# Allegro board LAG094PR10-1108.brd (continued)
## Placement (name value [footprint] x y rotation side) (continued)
PLH11  -  [5A_Z80_0805_2P]  156.75 63.52 270 bottom
PLM01  1UH_11A_20%_7X7X3_M  [L_7X7X3_M_2P]  19.27 98.76 90 bottom
PLM11  -  [5A_Z80_0805_2P]  26.67 110.05 180 bottom
PLZ1  0.47UH_NA__12.2A_20%  [L_5X5X3_M]  85.51 117.32 270 bottom
PLZ11  -  [5A_Z80_0805_2P]  87.28 125.69 270 bottom
PQ1  -  [FDV301N-G_SOT23-3]  74.94 147.12 270 top
PQ2  -  [MMST3904-7-F_SOT323-3]  79.54 143.25 0 top
PQ11  -  [2N7002KW_SOT323-3]  190.62 42.9 270 top
PQ12  -  [L2N7002DW1T1G_SC88-6]  182.99 66.22 180 top
PQ13  -  [2N7002KDW_SOT363-6]  184.55 64.41 0 top
PQB03  -  [2N7002KW_SOT323-3]  177.06 69.38 90 top
PQB11  -  [EMB04N03H_EDFN5X6-8-5]  165.91 63.3 90 top
PQB12  -  [EMB04N03H_EDFN5X6-8-5]  174.58 66.87 270 top
PQB13  -  [EMB04N03H_EDFN5X6-8-5]  175.81 54.12 90 bottom
PQB25  AON7506_DFN33-8-5  [AON7702L_DFN8-5]  185.44 48.57 270 bottom
PQB26  AON7408L_DFN8-5  [AON7702L_DFN8-5]  182.57 50.28 90 bottom
PQB28  -  [LMUN5113T1G_SOT323-3]  169.95 44.89 0 top
PQB29  -  [LTC015EUBFS8TL_UMT3F]  169.85 48.89 180 top
PQB31  2N7002KW_SOT323-3  [DMN65D8LW-7_SOT323-3]  190.41 49.57 0 top
PQB32  -  [RUM002N02GT2L_VMT3]  200.26 55.62 0 top
PQB33  -  [RUM002N02GT2L_VMT3]  196.76 54.94 0 top
PQG1  -  [AON6380_DFN5X6-8-5]  101.63 117.92 180 bottom
PQG2  AON6314_N_DFN56-8-5  [Q_N_DFN56-8-5]  91.73 123.44 0 bottom
PQM01  -  [AONH36334_DFN3X3A8-10]  23.89 106.18 0 bottom
PQZ1  -  [AONH36334_DFN3X3A8-10]  87.35 121.94 270 bottom
PR1  33_0402_5%  [R_0402]  78.95 148.59 0 top
PR3  100K_0402_1%  [R_0402]  78.95 147.76 0 top
PR4  10K_0402_1%  [R_0402]  81.25 145.11 270 top
PR5  2.2K_0402_5%  [R_0402]  82.44 148.59 0 top
PR6  15K_0402_1%  [R_0402]  79.87 146.3 180 top
PR7  100K_0402_1%  [R_0402]  80.79 142.93 0 top
PR9  16.2K_0402_1%  [R_0402]  114.22 38.29 180 bottom
PR31  0_0402_5%  [R_0402]  186.09 62.4 90 top
PR32  3.3K_1206_5%  [R_1206]  187.55 67.11 270 top
PR33  10K_0402_1%  [R_0402]  182.58 62.42 0 top
PR34  1M_0402_1%  [R_0402]  186.04 68 180 top
PR35  0_0402_5%  [R_0402]  184.36 62.48 0 top
PR36  1M_0402_1%  [R_0402]  183.24 68.13 180 top
PR37  100_0402_5%  [R_0402]  147.87 44.93 90 bottom
PR38  1M_0402_1%  [R_0402]  185.12 67.18 0 top
PR39  200_0402_5%  [R_0402]  164.91 39.17 0 top
PR40  100K_0402_1%  [R_0402]  181.64 62.47 90 top
PR41  10K_0402_1%  [R_0402]  165.82 40 180 top
PR42  100_0402_5%  [R_0402]  150.73 44.93 90 bottom
PR43  100K_0402_1%  [R_0402]  193.52 43.29 90 top
PR44  1M_0402_1%  [R_0402]  183.24 67.24 180 top
PR45  1M_0402_1%  [R_0402]  185.28 63.3 180 top
PR301  0_0603_5%  [R0603_0OHM]  166.85 61.59 180 bottom
PR302  499K_0402_1%  [R_0402]  170.65 55.75 270 bottom
PR303  150K_0402_1%  [R_0402]  170.58 56.57 0 bottom
PR304  10K_0402_1%  [R_0402]  171.62 57.34 180 bottom
PR305  4.7_1206_5%  [R_1206]  164.31 59.69 270 top
PR306  1K_0402_5%  [R_0402]  167.17 53.51 90 bottom
PR307  150K_0402_1%  [R_0402]  167.15 55.24 0 bottom
PR308  150K_0402_1%  [R_0402]  168.88 54.43 270 bottom
PR501  0_0603_5%  [R_0603]  206.66 76.64 270 bottom
PR502  0_0402_5%  [R0402_0OHM]  215.49 84.46 270 bottom
PR503  0_0402_5%  [R0402_0OHM]  204.33 82.74 180 bottom
PR504  10K_0402_1%  [R_0402]  202.47 81.61 270 bottom
PR505  4.7_1206_5%  [R_1206]  209.33 77.91 90 top
PR506  2.2K_0402_5%  [R_0402]  203.42 84.46 270 bottom
PR507  0_0402_5%  [R0402_0OHM]  210.03 84.59 270 bottom
PR508  1M_0402_5%  [R_0402]  216.32 83.55 90 bottom
PR509  1K_0402_5%  [R_0402]  206.03 84.46 270 bottom
PR510  150K_0402_1%  [R_0402]  206.04 82.74 180 bottom
PR511  150K_0402_1%  [R_0402]  204.25 83.55 90 bottom
PR1201  100K_0402_5%  [R_0402]  64.8 46.62 270 top
PR1202  10K_0402_1%  [R_0402]  59.8 44.89 180 top
PR1203  4.7_1206_5%  [R_1206]  63.79 38.16 90 top
PR1204  10K_0402_1%  [R_0402]  60.17 46.62 270 top
PR1205  0_0402_5%  [R_0402]  62.07 46.62 270 top
PR1206  1M_0402_5%  [R_0402]  63.03 45.7 90 top
PR1801  0_0402_5%  [R_0402]  46.82 28.68 0 bottom
PR1802  1M_0402_5%  [R_0402]  47.74 29.48 180 bottom
PR1803  100K_0402_5%  [R_0402]  49.51 27.68 180 bottom
PR1804  4.7_1206_5%  [R_1206]  50.71 33.71 270 top
PR1805  10K_0402_1%  [R_0402]  44.28 30.22 0 bottom
PR1807  20K_0402_1%  [R_0402]  45.2 29.4 180 bottom
PR1808  0_0402_5%  [R_0402]  46.82 27.68 0 bottom
PR2501  0_0402_5%  [R0402_0OHM]  37.96 125.92 180 bottom
PR2502  21.5K_0402_1%  [R_0402]  27.59 124.63 90 bottom
PR2503  10K_0402_1%  [R_0402]  26.77 125.55 270 bottom
PR2504  2.2_0402_1%  [R_0402]  36.11 120.39 180 bottom
PRB01  0.01_1206_1%  [R_1206_4P-D]  171.32 46.36 180 bottom
PRB02  0.01_1206_1%  [R_1206_4P-D]  177.36 60.94 0 top
PRB03  3M_0402_5%  [R_0402]  179.98 68.33 90 top
PRB04  1M_0402_1%  [R_0402]  180.87 69.26 270 top
PRB06  0_0402_5%  [R0402_0OHM]  166.25 68.54 90 top
PRB07  4.02K_0402_1%  [R_0402]  192.05 44.36 90 bottom
PRB08  4.02K_0402_1%  [R_0402]  179.09 68.33 90 top
PRB09  374K_0402_1%  [R_0402]  190.71 52.51 0 top
PRB10  52.3K_0402_1%  [R_0402]  191.63 51.62 180 top
PRB11  1_0402_5%  [R_0402]  189.7 52.64 0 bottom
PRB12  2_0402_5%  [R_0402]  189.7 51.75 0 bottom
PRB13  100K_0402_5%  [R_0402]  190.51 49.97 0 bottom
PRB14  0_0603_1%  [R0603_0OHM]  191.21 48.85 180 bottom
PRB15  10_0805_1%  [R_0805]  188.41 54.48 0 bottom
PRB16  47K_0402_1%  [R_0402]  195.46 53.91 90 bottom
PRB17  150K_0402_1%  [R_0402]  194.67 54.82 270 bottom
PRB18  200K_0402_1%  [R_0402]  195.49 53.78 180 top
PRB19  0_0402_5%  [R0402_0OHM]  196.25 54.82 270 bottom
PRB20  0_0402_5%  [R0402_0OHM]  197.04 54.82 270 bottom
PRB21  0_0402_5%  [R_0402]  197.85 54.69 270 bottom
PRB22  0_0402_5%  [R0402_0OHM]  198.66 53.78 90 bottom
PRB23  100K_0402_1%  [R_0402]  198.97 52.64 0 bottom
PRB24  100K_0402_1%  [R_0402]  198.97 51.77 0 top
PRB25  499K_0402_1%  [R_0402]  193.87 53.91 90 bottom
PRB26  768K_0402_1%  [R_0402]  193.89 55.53 90 bottom
PRB27  200K_0402_1%  [R_0402]  193.76 54.75 270 top
PRB28  100K_0402_1%  [R_0402]  199.88 50.86 180 top
PRB29  0_0402_5%  [R0402_0OHM]  199.88 50.86 180 bottom
PRB30  100_0402_5%  [R_0402]  198.94 49.08 90 top
PRB31  1K_0402_1%  [R_0402]  199.88 49.08 180 bottom
PRB32  0_0402_5%  [R0402_0OHM]  201.66 49.11 0 bottom
PRB35  100_0402_5%  [R_0402]  199.88 47.3 180 bottom
PRB36  2_0402_5%  [R_0402]  197.06 43.98 270 bottom
PRB37  0_0402_5%  [R0402_0OHM]  197.85 43.98 270 bottom
PRB38  22.6K_0402_1%  [R_0402]  195.25 45.22 270 bottom
PRB39  4.7_0402_5%  [R_0402]  191.22 45.3 270 bottom
PRB40  4.7_1206_5%  [R_1206]  181.97 50.5 270 top
PRB41  0_0603_5%  [R_0603]  168.07 46.95 270 top
PRB42  10K_0402_5%  [R_0402]  198.87 55.79 180 top
PRB43  160K_0402_1%  [R_0402]  198.03 54.67 270 top
PRB44  10K_0402_5%  [R_0402]  194.57 54.67 0 top
PRB45  100K_0402_1%  [R_0402]  189.75 46.59 0 top
PRG01  24.9K_0402_1%  [R_0402]  100.53 140.86 180 top
PRG02  11.3K_0402_1%  [R_0402]  100.53 141.69 180 top
PRG03  37.4K_0402_1%  [R_0402]  95.74 142.68 0 top
PRG04  84.5_0402_1%  [R_0402]  101.02 137.57 0 top
PRG05  240_0402_1%  [R_0402]  101.02 138.4 0 top
PRG06  365_0402_1%  [R_0402]  99.55 139.12 180 top
PRG07  130_0402_1%  [R_0402]  98.85 141.69 270 top
PRG08  866_0402_1%  [R_0402]  96.64 141.89 270 top
PRG09  100_0402_1%  [R_0402]  101.15 136.89 0 bottom
PRG10  2.2_0603_1%  [R_0603]  100.87 132.46 180 bottom
PRG11  0_0402_5%  [R0402_0OHM]  101.15 137.7 0 bottom
PRG12  20_0402_1%  [R_0402]  101.13 138.51 0 bottom
PRG13  20K_0402_1%  [R_0402]  98.64 138.3 0 top
PRG14  2K_0402_1%  [R_0402]  98.03 140.77 90 top
PRG15  8.25K_0402_1%  [R_0402]  95.82 140.98 90 top
PRG16  10K_0402_1%  [R_0402]  92.82 137.47 0 top
PRG17  68K_0402_1%  [R_0402]  95.46 142.24 0 bottom
PRG18  10K_0402_1%  [R_0402]  97.24 142.24 0 bottom
PRG19  100_0402_1%  [R_0402]  93.13 140.98 180 top
PRG20  4.7_1206_5%  [R_1206]  91.22 117.34 90 top
PRG21  1.13K_0402_1%  [R_0402]  91.3 138.44 90 bottom
PRG22  2.32K_0402_1%  [R_0402]  92.27 140.03 90 bottom
PRG23  10K_0402_1%  [R_0402]  92.2 141.75 0 bottom
PRG24  57.6K_0402_1%  [R_0402]  93.33 136.44 180 top
PRG25  1K_0402_1%  [R_0402]  101.94 139.23 180 top
PRG26  866_0402_1%  [R_0402]  92.41 135.62 0 top
PRG27  121K_0402_1%  [R_0402]  94.83 136.15 270 top
PRG28  33K_0402_1%  [R_0402]  92.99 137.41 180 bottom
PRG29  3.9_0603_1%  [R_0603]  92.87 135.12 90 bottom
PRG30  9.53K_0402_1%  [R_0402]  93.33 134.79 180 top
PRG31  1_0805_1%  [R_0805]  92.81 132.37 90 bottom
PRG32  100_0402_1%  [R_0402]  94.52 138.82 270 top
PRG33  8.2_0402_1%  [R_0402]  100.03 142.55 0 bottom
PRG34  100K_0402_1%  [R_0402]  101.13 136.08 0 bottom
PRG35  37.4_0402_1%  [R_0402]  92.41 133.97 0 top
PRG36  130_0402_1%  [R_0402]  94.94 141.18 90 top
PRG37  280_0402_1%  [R_0402]  99.55 137.47 180 top
PRG38  243_0402_1%  [R_0402]  97.46 142.45 0 top
PRG39  0_0402_1%  [R_0402]  92.07 138.23 0 bottom
PRG40  0_0402_5%  [R0402_0OHM]  93.13 141.77 180 top
PRG41  0_0402_5%  [R_0402]  101.13 139.57 0 bottom
PRG42  0_0402_5%  [R0402_0OHM]  92.24 139.38 0 top
PRG43  0_0402_5%  [R0402_0OHM]  93.15 140.19 180 top
PRG44  0_0603_5%  [R_0603]  98.46 133.73 0 bottom
PRG45  976_0402_1%  [R_0402]  92.2 139.21 0 bottom
PRG46  0.01_1206_1%  [R_1206_4P-D-NPM]  104.3 128 90 bottom
PRH01  0_0402_5%  [R0402_0OHM]  153.72 60.07 180 top
PRH02  1M_0402_1%  [R_0402]  152.8 59.18 0 top
PRH03  0_0402_5%  [R_0402]  149.28 57.26 90 bottom
PRH04  0_0402_5%  [R_0402]  150.07 58.17 270 bottom
PRH05  100K_0402_5%  [R_0402]  151.8 57.29 90 top
PRH06  10_0402_1%  [R_0402]  146.77 60.03 90 bottom
PRH07  4.7_1206_5%  [R_1206]  143.73 61.78 0 top
PRH08  7.5K_0402_1%  [R_0402]  153.4 58.2 270 bottom
PRH09  10K_0402_1%  [R_0402]  152.61 58.2 270 bottom
PRH11  2.2_0402_1%  [R_0402]  151.8 57.29 90 bottom
PRH12  1K_0402_1%  [R_0402]  155.11 58.21 180 bottom
PRM01  4.7_1206_5%  [R_1206]  18.64 103.12 0 top
PRM02  2.2_0603_5%  [R_0603]  23.85 113.34 270 top
PRM03  10.5K_0402_1%  [R_0402]  21.45 116.14 180 top
PRM04  5.1_0603_5%  [R_0603]  20.04 118.61 0 top
PRM05  2.2_0603_5%  [R_0603]  18.77 116.96 90 top
PRM06  10K_0402_1%  [R_0402]  23.28 121.36 270 top
PRM07  453K_0402_1%  [R_0402]  24.1 121.36 270 top
PRM08  0_0402_5%  [R0402_0OHM]  24.93 121.36 270 top
PRM09  0_0402_5%  [R0402_0OHM]  27.66 121.36 270 top
PRM10  6.04K_0402_1%  [R_0402]  29.43 118.11 180 top
PRM11  10K_0402_1%  [R_0402]  29.26 118.99 180 top
PRM12  0.01_1206_1%  [R_1206_4P-D-NPM]  26.65 110.23 180 top
PRZ01  0_0402_5%  [R0402_0OHM]  81.97 133.74 90 top
PRZ02  470K_0402_1%  [R_0402]  89.39 136.96 180 top
PRZ03  140K_0402_1%  [R_0402]  89.39 137.79 180 top
PRZ04  191K_0402_1%  [R_0402]  86.01 139.26 270 top
PRZ05  160_0402_1%  [R_0402]  89.04 131.96 0 top
PRZ06  240_0402_1%  [R_0402]  89.04 132.85 0 top
PRZ07  1.54K_0402_1%  [R_0402]  87.66 137.55 270 top
PRZ08  3.3K_0402_1%  [R_0402]  86.01 137.55 270 top
PRZ09  43.2K_0402_1%  [R_0402]  85.11 138.04 0 bottom
PRZ10  10K_0402_1%  [R_0402]  86.89 138.04 0 bottom
PRZ11  100_0402_1%  [R_0402]  89.24 131.5 0 bottom
PRZ12  100_0402_1%  [R_0402]  80.22 134.37 180 top
PRZ13  0_0402_5%  [R0402_0OHM]  89.24 132.39 0 bottom
PRZ14  20_0402_1%  [R_0402]  89.24 133.28 0 bottom
PRZ15  11.3K_0402_1%  [R_0402]  87.46 134.96 270 top
PRZ16  16K_0402_1%  [R_0402]  86.84 136.63 90 top
PRZ17  11K_0402_1%  [R_0402]  85.06 136.63 90 top
PRZ18  10K_0402_1%  [R_0402]  83.37 133.26 0 top
PRZ19  2.2_0603_1%  [R_0603]  88.24 129.6 270 bottom
PRZ20  1K_0402_1%  [R_0402]  89.32 135.26 270 top
PRZ21  560_0402_1%  [R_0402]  81.31 133.61 90 bottom
PRZ22  3.9_0603_1%  [R_0603]  81.7 131.34 90 bottom
PRZ23  4.7_1206_5%  [R_1206]  86.14 117.6 180 top
PRZ24  82.5K_0402_1%  [R_0402]  82.1 134.53 270 bottom
PRZ25  1_0805_1%  [R_0805]  83.22 126.53 90 bottom
PRZ26  866_0402_1%  [R_0402]  82.32 138.11 0 bottom
PRZ27  1K_0402_1%  [R_0402]  82.51 136.96 0 top
PRZ28  174K_0402_1%  [R_0402]  82 132.44 180 top
PRZ29  1.4K_0402_1%  [R_0402]  81.11 131.61 270 top
PRZ30  121K_0402_1%  [R_0402]  81.94 131.61 270 top
PRZ31  8.45K_0402_1%  [R_0402]  81.1 129.88 0 top
PRZ32  100_0402_1%  [R_0402]  83.19 134.07 0 top
PRZ33  8.2_0402_1%  [R_0402]  89.24 136.08 0 bottom
PRZ34  10K_0402_1%  [R_0402]  89.24 130.61 0 bottom
PRZ35  0_0402_1%  [R_0402]  86.83 138.36 0 top
PRZ36  220_0402_1%  [R_0402]  87.71 133.1 180 top
PRZ37  240_0402_1%  [R_0402]  85.06 138.35 90 top
PRZ38  174_0402_1%  [R_0402]  82.01 129.05 180 top
PRZ39  0_0402_5%  [R0402_0OHM]  82.51 136.14 0 top
PRZ40  0_0402_5%  [R_0402]  90.08 134.35 90 top
PRZ41  10K_0402_1%  [R_0402]  88.43 136.15 270 top
PRZ42  953_0402_1%  [R_0402]  82.2 135.31 180 bottom
PRZ43  0_0402_5%  [R0402_0OHM]  80.22 133.59 180 top
PRZ44  953_0402_1%  [R_0402]  81.29 136.1 0 bottom
PRZ45  0.01_1206_1%  [R_1206_4P-D-NPM]  90.33 128.34 270 bottom
PU301  -  [SY8286BRAC_QFN20_3X3]  166.9 59.9 270 bottom
PU501  -  [SY8288CRAC_QFN20_3X3]  206.36 78.01 90 bottom
PU1201  -  [RT8061AZQW_WDFN10_3X3]  64.19 42.3 90 top
PU1801  -  [RT8061AZQW_WDFN10_3X3]  47.75 33.51 270 bottom
PU2501  -  [RT9059GSP_SO8]  35.38 125.47 270 bottom
PUB01  -  [ISL95522HRZ-T_TQFN32_4X4]  196.7 47.79 90 bottom
PUG1  -  [RT3601EAGQW_WQFN28_4X4]  99.11 138.48 180 bottom
PUH01  -  [RT6226AGQUF_UQFN12_3X3]  148.19 61.22 0 bottom
PUM01  -  [RT8207PGQW_WQFN20_3X3]  26.48 116.29 90 top
PUZ1  -  [RT3601EAGQW_WQFN28_4X4]  87.75 134.23 180 bottom
Q6  -  [LN2306LT1G_SOT23-3]  85.19 36.8 180 bottom
Q7  -  [DDTA144VCA-7-F_SOT23-3]  81.25 36.8 180 bottom
Q8  -  [LN2306LT1G_SOT23-3]  89.12 36.8 180 bottom
Q9  -  [LN2306LT1G_SOT23-3]  131.8 30.82 0 bottom
Q10  S TR L2N7002DW1T1G 2N SC88-6  [DMN66D0LDW-7_SOT363-6]  118.15 33.32 90 bottom
Q11  S TR L2N7002DW1T1G 2N SC88-6  [DMN66D0LDW-7_SOT363-6]  70.39 112.15 270 bottom
Q12  NTK3139PT1G_SOT723-3  [2N7002K_SOT23-3]  113.98 32.19 270 bottom
Q13  -  [2N7002K_SOT23-3]  111.5 27.87 270 bottom
Q14  -  [LMBT3904LT1G_SOT23-3]  59.41 55.91 0 top
Q17  S TR L2N7002DW1T1G 2N SC88-6  [DMN66D0LDW-7_SOT363-6]  10.58 123.52 270 top
Q19  -  [DDTA144VCA-7-F_SOT23-3]  6.61 122.74 270 top
Q22  -  [LN2306LT1G_SOT23-3]  6.61 118.8 270 top
Q25  S TR L2N7002DW1T1G 2N SC88-6  [DMN66D0LDW-7_SOT363-6]  12.17 120.79 270 top
Q57  -  [MESS138W-G_SOT323-3]  26.58 96.71 90 top
Q58  -  [MESS138W-G_SOT323-3]  26.58 93.34 90 top
Q5027  -  [MESS138W-G_SOT323-3]  208.82 55.49 90 top
Q5029  -  [DDTA144VCA-7-F_SOT23-3]  11.18 121.28 90 bottom
QA2  -  [LN2306LT1G_SOT23-3]  38.67 22.35 90 top
QC1  2N7002K_SOT23  [2N7002_SOT23-3]  105.08 50.88 180 top
QC2  L2N7002DW1T1G 2N SOT-363  [2N7002KDWH_SOT363-6]  108.19 63.01 180 bottom
QC3  AO3414_SOT23-3  [AP2302GN-HF_SOT23-3]  109.38 92.92 0 bottom
QC9  2N7002K_SOT23  [2N7002_SOT23-3]  109.8 60 270 top
QC10  2N7002K_SOT23  [2N7002_SOT23-3]  105.04 55.52 180 top
QG1  -  [DMN66D0LDW-7_SOT363-6]  24.48 87.67 90 bottom
QS1  L2N7002DW1T1G  [DMN66D0LDW-7_SOT363-6]  181.32 43 270 bottom
QW1  -  [L2N7002WT1G_SC-70-3]  64.36 132.08 180 top
R3  0_0603_5%  [R_0603]  215.91 56.45 0 top
R4  0_0603_5%  [R_0603]  215.24 27.81 0 top
R5  10K_0402_5%  [R_0402]  212.7 56.52 270 top
R6  0_0402_5%  [R0402_0OHM]  211.87 55.61 90 top
R7  0_0603_5%  [R0603_0OHM]  218.98 27.81 180 top
R8  0_0402_5%  [R0402_0OHM]  209.85 47.11 180 top
R9  0_0402_5%  [R_0402]  207.98 46.29 0 top
R10  100K_0402_5%  [R_0402]  222.16 58.75 270 top
R13  0_0603_5%  [R_0603]  214.47 40 180 top
R17  0_0402_5%  [R_0402-NPM]  206.17 48.06 180 bottom
R18  0_0402_5%  [R_0402-NPM]  206.17 48.83 180 bottom
R19  33_0402_5%  [R_0402]  211.81 41.13 90 top
R20  0_0402_5%  [R_0402]  201.58 42.81 270 bottom
R21  0_0402_5%  [R_0402]  200.82 42.81 270 bottom
R22  100_0402_5%  [R_0402]  224.96 60.76 180 top
R24  100K_0402_5%  [R_0402]  84.79 40.51 0 bottom
R25  1K_0402_5%  [R_0402]  78.77 36.77 270 bottom
R26  51K_0402_5%  [R_0402]  100.19 35.62 180 bottom
R27  100K_0402_5%  [R_0402]  101.06 35.7 270 bottom
R28  18.7K_0402_1%  [R_0402]  80.68 50.34 90 top
R29  2K_0402_1%  [R_0402]  80.68 49.54 270 top
R31  4.7K_0402_5%  [R_0402]  123.59 33.14 0 bottom
R32  4.7K_0402_5%  [R_0402]  126.28 33.14 180 bottom
R33  4.7K_0402_5%  [R_0402]  121.07 33.96 90 bottom
R34  4.7K_0402_5%  [R_0402]  117.19 34.43 270 bottom
R35  0_0402_5%  [R_0402]  110.08 33.79 270 bottom
R36  0_0603_5%  [R_0603]  115.86 34.29 270 bottom
R37  100_0603_5%  [R_0603]  112.43 29.59 0 bottom
R38  20K_0402_1%  [R_0402]  109.19 32.01 270 bottom
R39  10K_0402_5%  [R_0402]  132.25 27.05 180 bottom
R40  4.7K_0402_5%  [R_0402]  115.92 31.82 270 bottom
R41  100K_0402_5%  [R_0402]  121.07 33.09 270 bottom
R46  2.2K_0402_5%  [R_0402]  120.25 32.25 180 bottom
R47  2.2K_0402_5%  [R_0402]  117.62 32.25 0 bottom
R48  2.2K_0402_5%  [R_0402]  71.34 111.36 90 bottom
R49  2.2K_0402_5%  [R_0402]  67.6 111.58 270 bottom
R57  10K_0402_5%  [R_0402]  222.16 55.23 90 top
R68  200_0402_5%  [R_0402]  5.69 125.1 270 top
R69  200_0402_5%  [R_0402]  4.86 125.1 270 top
R72  100K_0402_5%  [R_0402]  220.38 49.4 90 top
R74  0_0603_5%  [R_0603]  222.47 44.64 270 top
R77  0_0402_5%  [R0402_0OHM]  43.09 26.54 90 bottom
R78  0_0402_5%  [R_0402]  11.21 120.4 270 top
R79  100K_0402_5%  [R_0402]  12.66 118.49 0 top
R80  100K_0402_5%  [R_0402]  10.38 118.6 90 top
R83  0_0402_5%  [R_0402]  213.41 46.92 180 top
R84  0_0201_5%  [R_0201]  202.95 43.37 180 top
R85  0_0201_5%  [R_0201]  202.95 44.19 180 top
R86  4.7K_0402_5%  [R_0402]  204.77 43.37 180 top
R87  4.7K_0402_5%  [R_0402]  204.77 44.19 180 top
R100  10K_0402_5%  [R_0402]  215.11 54.62 270 top
R131  0_0402_5%  [R_0402]  212.77 43.43 180 top
R182  0_0402_5%  [R_0402]  27.14 26.01 180 top
R300  0_0402_5%  [R_0402]  42.26 26.53 90 bottom
R301  0_0603_5%  [R0603_0OHM]  206.47 57.59 0 top
R302  100_0402_5%  [R_0402]  213.15 48 180 top
R303  100_0402_5%  [R_0402]  213.09 49.4 180 top
R304  100_0402_5%  [R_0402]  213.09 50.99 180 top
R926  100K_0402_5%  [R_0402]  152.57 54.76 270 top
R927  100K_0402_5%  [R_0402]  151.75 53.84 90 top
R5216  10K_0402_5%  [R_0402]  11.29 117.79 180 top
R5217  100K_0402_5%  [R_0402]  207.09 47.11 0 top
R5218  100K_0402_5%  [R_0402]  215.69 48.89 180 top
R5220  0_0402_5%  [R_0402]  218.66 49.33 0 top
R5221  0_0603_5%  [R_0603]  217.84 43.87 0 top
R5222  0_0603_5%  [R_0603]  220.63 42.54 180 top
RA1  0_0805_5%  [R0805_0OHM]  37.65 7.17 180 top
RA8  100K_0402_5%  [R_0402]  35.42 9.14 180 top
RA30  33_0402_5%  [R_0402]  36.43 13.65 180 top
RA31  1K_0402_5%  [R_0402]  36.43 17.97 180 top
RA32  0_0402_5%  [R_0402]  36.43 16.44 180 top
RA33  0_0402_5%  [R0402_0OHM]  39.34 8.49 90 top
RA34  0_0603_5%  [R0603_0OHM]  26.83 21.52 270 top
RA35  0_0402_5%  [R0402_0OHM]  34.72 20.57 180 top
RA36  0_0402_5%  [R0402_0OHM]  36.41 20 0 top
RA37  0_0402_5%  [R_0402]  30.51 20.43 90 top
RA38  0_0402_5%  [R_0402]  21.69 9.22 270 top
RA39  0_0402_5%  [R_0402]  26.96 8.01 270 top
RA40  100K_0402_5%  [R_0402]  33.74 17.97 0 top
RA41  0_0402_5%  [R_0402]  29.69 20.43 90 top
RA42  BLM15PD800SN1D_2P  [MURAT_BLM15PD600SN1D_2P]  28.09 5.65 180 top
RA43  BLM15PD800SN1D_2P  [MURAT_BLM15PD600SN1D_2P]  23.9 1.65 180 top
RA45  BLM15PD800SN1D_2P  [MURAT_BLM15PD600SN1D_2P]  28.09 4.38 180 top
RA46  33_0402_5%  [R_0402]  36.75 10.41 180 top
RA47  100K_0402_5%  [R_0402]  26.12 16.82 0 top
RA48  10K_0402_5%  [R_0402]  35.52 17.2 0 top
RA49  BLM15PD800SN1D_2P  [MURAT_BLM15PD600SN1D_2P]  25.99 2.8 180 top
RA50  33_0402_5%  [R_0402]  37.7 12.19 180 top
RA51  200K_0402_1%  [R_0402]  32.91 19.74 0 top
RA52  4.7K_0402_5%  [R_0402]  21.8 13.77 0 top
RA53  4.7K_0402_5%  [R_0402]  21.8 12.25 0 top
RA54  10K_0402_5%  [R_0402]  17.18 11.98 90 bottom
RA55  1K_0402_5%  [R_0402]  23.96 13.2 0 top
RA56  2.2K_0402_5%  [R_0402]  19.41 13.97 180 top
RA57  10K_0402_5%  [R_0402]  18.07 10.3 270 bottom
RA58  10_0402_1%  [R_0402]  24.88 14.03 180 top
RA59  1K_0402_5%  [R_0402]  23.96 14.85 0 top
RA60  2.2K_0402_5%  [R_0402]  20.35 13.95 90 top
RA61  10_0402_1%  [R_0402]  24.88 12.44 180 top
RA62  0_0402_5%  [R0402_0OHM]  17 15.55 180 top
RA63  0_0805_5%  [R_0805]  23.97 19.08 90 top
RA65  0_0402_5%  [R0402_0OHM]  39.29 15.49 180 top
RB1  0_0402_5%  [R_0402]  207.82 58.61 180 top
RB2  0_0402_5%  [R_0402]  217.27 55.44 270 top
RB3  0_0402_5%  [R_0402]  215.93 55.44 270 top
RB4  0_0402_5%  [R_0402]  100.8 124.2 0 top
RB5  0_0402_5%  [R_0402]  162.15 47.04 90 bottom
RB6  0_0402_5%  [R_0402]  170.42 47.94 180 bottom
RB7  0_0402_5%  [R_0402]  86.14 122.09 90 top
RB8  0_0402_5%  [R_0402]  155.53 42.92 0 top
RB9  0_0402_5%  [R_0402]  181.31 39.87 0 bottom
RB10  0_0402_5%  [R_0402]  27.86 106.61 180 bottom
RB12  0_0402_5%  [R_0402]  158.29 61.9 90 bottom
RC1  100_0402_1%  [R_0402]  87.64 60.58 90 top
RC2  2.2K_0402_5%  [R_0402]  103.46 80.2 0 top
RC3  2.2K_0402_5%  [R_0402]  103.46 79.37 0 top
RC4  1K_0402_5%  [R_0402]  102.21 86.66 90 bottom
RC5  0_0402_5%  [R_0402]  102.21 85.86 270 bottom
RC6  10K_0402_5%  [R_0402]  109.17 73.66 180 top
RC7  10K_0402_5%  [R_0402]  102.17 71.23 180 bottom
RC8  4.7K_0402_5%  [R_0402]  98.26 66.8 0 bottom
RC9  4.7K_0402_5%  [R_0402]  102.32 65.65 0 bottom
RC10  1K_0402_5%  [R_0402]  108.25 72.83 0 top
RC11  4.7K_0402_5%  [R_0402]  102.14 70.48 270 bottom
RC12  10K_0402_5%  [R_0402]  102.32 66.42 0 bottom
RC13  33_0402_5%  [R_0402]  100 67.94 180 bottom
RC14  33_0402_5%  [R_0402]  100 68.7 180 bottom
RC15  33_0402_5%  [R_0402]  100 69.46 180 bottom
RC16  249_0402_1%  [R_0402]  99.08 70.23 0 bottom
RC17  1K_0402_1%  [R_0402]  101.32 69.57 90 bottom
RC18  200_0402_1%  [R_0402]  90.08 62.57 90 top
RC19  20_0402_1%  [R_0402]  98.89 74.99 0 bottom
RC20  20_0402_1%  [R_0402]  98.89 77.27 0 bottom
RC21  20_0402_1%  [R_0402]  98.89 76.51 0 bottom
RC22  20_0402_1%  [R_0402]  98.89 75.75 0 bottom
RC23  20_0402_1%  [R_0402]  109.89 70.85 270 top
RC24  33_0402_5%  [R_0402]  101.77 76.38 0 bottom
RC25  200_0402_1%  [R_0402]  92.22 70.99 0 top
RC30  39K_0402_5%  [R_0402]  102.97 80.18 90 bottom
RC31  1K_0402_5%  [R_0402]  106.64 72.39 0 bottom
RC32  1K_0402_5%  [R_0402]  107.79 82.72 0 bottom
RC33  150_0402_1%  [R_0402]  79.52 60.65 0 top
RC34  0_0402_5%  [R0402_0OHM]  103.02 72.26 0 bottom
RC35  0_0402_5%  [R0402_0OHM]  103.79 79.23 90 bottom
RC36  33_0402_5%  [R_0402]  99.08 70.99 0 bottom
RC37  33_0402_5%  [R_0402]  109.58 72.13 180 bottom
RC38  110_0402_1%  [R_0402]  69.88 64.63 90 bottom
RC39  110_0402_1%  [R_0402]  69 65.54 270 bottom
RC40  0_0402_5%  [R_0402]  69.39 62.23 180 bottom
RC41  1K_0402_1%  [R_0402]  30.49 85.78 0 top
RC42  0_0402_5%  [R0402_0OHM]  31.41 84.96 180 top
RC43  10K_0402_5%  [R_0402]  98.94 86.42 0 bottom
RC45  100K_0402_5%  [R_0402]  98.38 87.31 0 bottom
RC46  100K_0402_5%  [R_0402]  96.74 87.99 90 bottom
RC47  1K_0402_5%  [R_0402]  104.38 81.53 180 top
RC48  1K_0402_5%  [R_0402]  98.46 88.95 90 bottom
RC49  0_0402_5%  [R_0402]  101.76 89.14 90 bottom
RC50  100K_0402_5%  [R_0402]  105.44 89.26 90 bottom
RC51  100K_0402_5%  [R_0402]  100.94 90.03 90 bottom
RC52  0_0402_5%  [R_0402]  106.03 79.56 180 top
RC53  0_0402_5%  [R_0402]  108.56 78.21 90 top
RC54  0_0402_5%  [R_0402]  106.03 80.39 180 top
RC55  100K_0402_5%  [R_0402]  105.11 81.53 0 top
RC56  100K_0402_5%  [R_0402]  108.3 75.32 270 top
RC57  100K_0402_5%  [R_0402]  105.25 72.78 270 top
RC58  1K_0402_5%  [R_0402]  98.38 88.13 0 bottom
RC59  240_0402_1%  [R_0402]  95.09 88.91 270 bottom
RC60  220_0402_5%  [R_0402]  95.92 87.99 90 bottom
RC61  68_0402_5%  [R_0402]  95.08 89.72 0 bottom
RC62  10M_0402_5%  [R_0402]  112.16 57.65 0 top
RC63  1K_0402_5%  [R_0402]  112.16 56.83 0 top
RC64  10K_0402_5%  [R_0402]  105.62 47.11 0 top
RC65  20K_0402_5%  [R_0402]  106.65 58.11 180 top
RC66  20K_0402_5%  [R_0402]  106.65 60.18 90 top
RC67  10M_0402_5%  [R_0402]  103.44 68.56 90 top
RC68  200K_0402_5%  [R_0402]  86 50.16 0 bottom
RC69  1K_0402_5%  [R_0402]  93.44 87.99 90 bottom
RC70  1K_0402_5%  [R_0402]  94.27 87.99 90 bottom
RC71  0_0402_5%  [R_0402]  86.08 51.89 270 bottom
RC72  0_0402_5%  [R_0402]  86.9 51.89 270 bottom
RC73  330K_0402_5%  [R_0402]  106.66 59.43 180 top
RC75  0_0402_5%  [R_0402]  84.24 54.11 270 bottom
RC76  0_0402_5%  [R_0402]  85.06 54.11 270 bottom
RC77  113_0402_1%  [R_0402]  87.66 63.04 90 top
RC78  56_0402_1%  [R_0402]  90.33 58.91 90 top
RC79  10K_0402_5%  [R_0402]  93.06 90.62 270 bottom
RC80  10K_0402_5%  [R_0402]  92.3 90.62 270 bottom
RC81  100_0402_1%  [R_0402]  91.16 59.83 270 top
RC82  150_0402_1%  [R_0402]  103.95 76.94 0 top
RC83  2.2K_0402_5%  [R_0402]  108.12 65.72 180 bottom
RC84  2.2K_0402_5%  [R_0402]  107.46 61.91 0 bottom
RC85  10K_0402_5%  [R_0402]  103.78 74.43 0 top
RC86  75K_0402_5%  [R_0402]  108.24 69.45 90 top
RC87  10K_0402_5%  [R_0402]  111.92 69.79 270 top
RC88  20K_0402_5%  [R_0402]  111.04 68 180 top
RC89  2.2K_0402_5%  [R_0402]  105.89 65.16 270 bottom
RC90  2.2K_0402_5%  [R_0402]  105.89 62.59 90 bottom
RC91  10K_0402_5%  [R_0402]  92.43 87.07 270 bottom
RC92  100K_0402_5%  [R_0402]  110.73 89.15 180 bottom
RC93  1K_0402_1%  [R_0402]  106.07 92.83 0 bottom
RC94  10K_0402_5%  [R_0402]  108.1 89.15 0 bottom
RC95  4.7K_0402_5%  [R_0402]  90.46 89.52 90 bottom
RC96  4.7K_0402_5%  [R_0402]  90.46 88.27 270 bottom
RC97  4.7K_0402_5%  [R_0402]  89.06 89.45 90 bottom
RC98  4.7K_0402_5%  [R_0402]  89.7 88.27 270 bottom
RC99  10K_0402_5%  [R_0402]  88.24 89.45 90 bottom
RC100  4.7K_0402_5%  [R_0402]  88.24 88.27 270 bottom
RC101  4.7K_0402_5%  [R_0402]  106.52 87.32 270 bottom
RC102  0_0402_5%  [R_0402]  107.91 87.37 0 bottom
RC103  4.7K_0402_5%  [R_0402]  109.6 76.07 180 top
RC104  4.7K_0402_5%  [R_0402]  110.33 76.07 0 top
RC105  4.7K_0402_5%  [R_0402]  109.6 76.84 180 top
RC106  4.7K_0402_5%  [R_0402]  110.33 76.84 0 top
RC107  10K_0402_5%  [R_0402]  104.86 76.18 180 top
RC108  10K_0402_5%  [R_0402]  91.41 87.36 90 bottom
RC109  10K_0402_5%  [R_0402]  91.41 90.43 270 bottom
RC110  1K_0402_5%  [R_0402]  103.23 64.89 180 bottom
RC111  51_0402_5%  [R_0402]  79.98 96.38 90 bottom
RC112  51_0402_5%  [R_0402]  78.46 95.61 90 bottom
RC113  10_0402_1%  [R_0402]  79.22 96.38 90 bottom
RC114  100_0402_1%  [R_0402]  79.21 98.04 0 bottom
RC115  51_0402_5%  [R_0402]  77.63 95.61 90 bottom
RC116  51_0402_5%  [R_0402]  79.22 95.39 270 bottom
RC117  10K_0402_5%  [R_0402]  111.87 78.48 180 top
RC119  10K_0402_5%  [R_0402]  82.9 101.2 90 bottom
RC120  10K_0402_5%  [R_0402]  113.43 75.88 0 top
RC121  10K_0402_5%  [R_0402]  101.38 86.66 90 bottom
RC122  0_0603_5%  [R_0603]  89.25 55.3 90 top
RC123  0_0603_5%  [R_0603]  65.06 55.3 90 top
RC124  0_0603_5%  [R_0603]  80.81 91.88 270 top
RC125  0_0805_5%  [R_0805]  82.51 51.86 90 top
RC126  0_0402_5%  [R0402_0OHM]  78.33 55.04 90 top
RC127  0_0603_5%  [R0603_0OHM]  82.39 54.99 180 top
RC128  0_0402_5%  [R0402_0OHM]  83.03 60.24 90 top
RC129  0_0402_5%  [R0402_0OHM]  84.3 60.24 90 top
RC130  0_0402_5%  [R0402_0OHM]  86.38 62.74 90 top
RC131  0_0603_5%  [R0603_0OHM]  79.41 55.11 90 top
RC132  0_0603_5%  [R0603_0OHM]  84.81 88.96 0 top
RC133  0_0603_5%  [R0603_0OHM]  82.2 89.28 180 top
RC134  0_0402_5%  [R0402_0OHM]  83.35 83.38 270 top
RC135  0_0402_5%  [R0402_0OHM]  83.36 84.13 180 top
RC136  0_0402_5%  [R0402_0OHM]  82.58 83.38 270 top
RC138  10K_0402_5%  [R_0402]  116.81 65.51 90 top
RC139  0_0402_5%  [R_0402]  68.04 114.42 180 top
RC140  10K_0402_5%  [R_0402]  66.28 109.66 180 top
RC141  10K_0402_5%  [R_0402]  64.28 113.28 0 top
RC142  1K_0402_5%  [R_0402]  68.73 109.66 0 top
RC143  0_0402_5%  [R_0402]  69.83 113.15 180 top
RC144  0_0402_5%  [R_0402]  67.34 115.25 180 top
RC145  1K_0402_5%  [R_0402]  65.43 114.42 0 top
RC148  0_0402_5%  [R_0402]  69.76 127.55 90 top
RC151  1K_0402_5%  [R_0402]  106.7 86.48 0 top
RC155  100_0402_1%  [R_0402]  64.28 96.52 0 top
RC156  100_0402_1%  [R_0402]  60.79 96.52 0 top
RC157  0_0402_5%  [R_0402]  69.39 61.4 180 bottom
RC158  100K_0402_5%  [R_0402]  99.87 80.26 180 bottom
RC159  100K_0402_5%  [R_0402]  99.87 79.5 180 bottom
RC160  100K_0402_5%  [R_0402]  99.87 78.74 180 bottom
RC161  33_0402_5%  [R_0402]  102.8 73.44 0 bottom
RC162  33_0402_5%  [R_0402]  101.13 72.79 45 bottom
RC163  33_0402_5%  [R_0402]  102.74 74.42 0 bottom
RC164  33_0402_5%  [R_0402]  102.74 75.18 0 bottom
RC165  10K_0402_5%  [R_0402]  105.77 85.02 180 top
RC166  10K_0402_5%  [R_0402]  105.77 85.78 180 top
RC167  10K_0402_5%  [R_0402]  105.77 84.26 180 top
RC168  10K_0402_5%  [R_0402]  105.77 89.02 180 top
RC169  10K_0402_5%  [R_0402]  105.77 87.37 180 top
RC170  10K_0402_5%  [R_0402]  105.77 86.55 180 top
RC171  10K_0201_5%  [R_0201]  82.08 107.03 270 bottom
RC172  10K_0201_5%  [R_0201]  82.71 106.45 90 bottom
RC173  10K_0201_5%  [R_0201]  81.44 107.03 270 bottom
RC174  10K_0201_5%  [R_0201]  80.81 106.45 90 bottom
RC175  10K_0402_5%  [R_0402]  105.77 88.2 180 top
RC176  10K_0402_5%  [R_0402]  99.87 81.02 180 bottom
RC203  10K_0402_5%  [R_0402]  111.87 79.31 180 top
RC213  100K_0402_5%  [R_0402]  221.08 35.73 90 top
RC1143  0_0402_5%  [R0402_0OHM]  101.38 85.86 270 bottom
RC1146  10K_0402_5%  [R_0402]  109.15 58.1 180 bottom
RC1147  0_0201_5%  [R_0201]  107.54 57.37 270 bottom
RC1148  10K_0402_5%  [R_0402]  109.15 58.92 180 bottom
RC1149  0_0201_5%  [R0201_0OHM]  108.64 53.72 0 top
RC1150  0_0402_5%  [R_0402]  58.14 113.33 90 top
RC1151  1K_0402_5%  [R_0402]  55.14 116.23 0 top
RC1152  100K_0402_5%  [R_0402]  58.14 114.98 90 top
RD1  0_0402_5%  [R_0402]  32.13 44.56 0 top
RD2  0_0402_5%  [R_0402]  31.33 44.56 180 top
RD3  0_0402_5%  [R_0402]  30.82 68.84 270 top
RD4  0_0402_5%  [R0402_0OHM]  33.04 43.73 180 top
RD5  0_0402_5%  [R0402_0OHM]  30.41 43.73 0 top
RD6  0_0402_5%  [R0402_0OHM]  31.65 67.93 90 top
RD9  2_0402_1%  [R_0402]  30.82 64.5 90 top
RD10  3.65K_0402_1%  [R_0402]  31.65 64.5 90 top
RD11  24.9_0402_1%  [R_0402]  31.65 62.72 90 top
RD12  3.65K_0402_1%  [R_0402]  31.66 66.22 180 top
RD23  240_0402_1%  [R_0402]  31.94 77.53 180 top
RD36  240_0402_1%  [R_0402]  35.28 73.7 180 top
RD37  240_0402_1%  [R_0402]  30.49 82.04 0 top
RE1  47K_0402_5%  [R_0402]  131.59 35.3 0 bottom
RE4  0_0603_5%  [R_0603]  116.43 52.76 90 bottom
RE5  0_0402_5%  [R0402_0OHM]  129.83 34.4 90 bottom
RE7  0_0402_5%  [R_0402]  138.62 42.98 180 bottom
RE8  0_0402_5%  [R_0402]  136.83 40.51 180 bottom
RE11  0_0402_5%  [R_0402]  127.8 55.61 90 bottom
RE12  0_0603_5%  [R_0603]  133 50.22 180 top
RE13  0_0603_5%  [R_0603]  129.13 50.22 0 top
RE14  100K_0402_1%  [R_0402]  116 38.29 180 bottom
RE15  0_0402_1%  [R_0402]  115.08 37.46 0 bottom
RE19  0_0402_5%  [R0402_0OHM]  121.05 56.95 0 bottom
RE20  0_0402_5%  [R0402_0OHM]  121.05 57.78 0 bottom
RE21  0_0402_5%  [R_0402]  124.63 56.45 180 bottom
RE25  0_0402_5%  [R_0402]  132.1 51.3 0 top
RE26  33_0402_5%  [R_0402]  136.95 48.06 180 bottom
RE27  10K_0402_5%  [R_0402]  115.4 41.4 0 bottom
RE28  10K_0402_5%  [R_0402]  116.32 42.22 180 bottom
RE29  100K_0402_5%  [R_0402]  135.91 39.68 0 bottom
RE30  100K_0402_5%  [R_0402]  115.65 46.97 0 bottom
RE31  0_0402_5%  [R_0402]  129.32 57.92 270 bottom
RE32  100K_0402_5%  [R_0402]  124.29 57.72 0 bottom
RE34  100K_0402_5%  [R_0402]  127.03 55.74 90 bottom
RE35  100K_0402_5%  [R_0402]  118.91 55.16 90 bottom
RE36  2.2K_0402_5%  [R_0402]  115.53 43.48 0 bottom
RE37  2.2K_0402_5%  [R_0402]  115.53 44.24 0 bottom
RE38  2.2K_0402_5%  [R_0402]  114.65 44.5 90 bottom
RE39  2.2K_0402_5%  [R_0402]  115.59 46.02 0 bottom
RE40  0_0402_5%  [R_0402]  125.51 56.65 270 bottom
RE41  10K_0402_5%  [R_0402]  126.32 51.05 0 top
RE42  0_0402_5%  [R0402_0OHM]  115.41 34.98 45 top
RE43  0_0603_5%  [R_0603]  115.22 52.95 90 bottom
RE53  10K_0402_5%  [R_0402]  124.6 56.27 270 top
RE54  100K_0402_5%  [R_0402]  128.51 57.02 180 top
RE55  100K_0402_5%  [R_0402]  126.27 55.74 90 bottom
RG47  10K_0402_5%  [R_0402]  28.1 88.65 270 bottom
RG48  10K_0402_5%  [R_0402]  23.53 87.23 90 bottom
RG56  100K_0402_5%  [R_0402]  22.13 86.69 270 bottom
RG59  5.6_0402_1%  [R_0402]  19.73 94.61 180 top
RG60  5.6_0402_1%  [R_0402]  19.73 93.72 180 top
RG61  5.6_0402_1%  [R_0402]  19.73 95.56 180 top
RG63  5.6_0402_1%  [R_0402]  19.73 96.45 180 top
RG64  5.6_0402_1%  [R_0402]  19.73 91.83 180 top
RG65  5.6_0402_1%  [R_0402]  19.73 92.72 180 top
RG66  5.6_0402_1%  [R_0402]  19.73 89.86 180 top
RG67  150_0402_5%  [R_0402]  17.37 93.71 90 top
RG68  150_0402_5%  [R_0402]  17.37 96.4 270 top
RG69  150_0402_5%  [R_0402]  17.37 92.79 270 top
RG70  5.6_0402_1%  [R_0402]  19.73 90.75 180 top
RG71  150_0402_5%  [R_0402]  17.37 90.83 270 top
RG102  470_0402_5%  [R_0402]  21.74 91.75 0 bottom
RG103  470_0402_5%  [R_0402]  21.74 92.64 0 bottom
RG104  470_0402_5%  [R_0402]  21.74 93.66 0 bottom
RG105  470_0402_5%  [R_0402]  21.74 94.55 0 bottom
RG106  470_0402_5%  [R_0402]  21.74 89.85 0 bottom
RG107  470_0402_5%  [R_0402]  21.74 90.74 0 bottom
RG108  470_0402_5%  [R_0402]  21.74 95.5 0 bottom
RG109  470_0402_5%  [R_0402]  21.74 96.39 0 bottom
RI13  2.2K_0402_5%  [R_0402]  27.22 95.05 180 top
RI14  2.2K_0402_5%  [R_0402]  26.27 91.94 180 top
RL2  2.49K_0402_1%  [R_0402]  22.65 82.16 180 bottom
RL3  1K_0402_5%  [R_0402]  24.19 88.53 270 top
RL4  15K_0402_5%  [R_0402]  23.43 87.61 90 top
RL5  0_0603_5%  [R0603_0OHM]  18.07 88.83 0 top
RL6  100K_0402_5%  [R_0402]  23.16 75.81 180 top
RL7  10K_0402_5%  [R_0402]  20.11 75.88 180 bottom
RL8  33_0402_5%  [R_0402]  17.05 85.61 270 top
RL9  33_0402_5%  [R_0402]  17.05 82.91 90 top
RL13  0_0402_5%  [R0402_0OHM]  27.91 82.47 90 top
RL17  0_0402_5%  [R_0402]  16.67 87.23 90 top
RL19  75_0603_5%  [R_0603]  18.51 61.4 270 bottom
RL20  75_0603_5%  [R_0603]  19.78 61.4 270 top
RL21  0_0603_5%  [R_0603]  21.05 87.56 90 bottom
RL22  75_0603_5%  [R_0603]  18.51 61.4 270 top
RL23  75_0603_5%  [R_0603]  19.78 61.4 270 bottom
RL24  0_0402_5%  [R_0402]  24.27 85.12 270 bottom
RM1  0_0603_5%  [R_0603]  104.56 46.92 270 top
RM2  0_0603_5%  [R_0603]  108.75 34.29 90 top
RM12  100K_0402_5%  [R_0402]  111.41 52.59 270 top
RM13  20K_0402_5%  [R_0402]  108.1 52.57 0 top
RM14  10_0402_1%  [R_0402]  109.83 52.59 270 top
RM15  10_0402_1%  [R_0402]  110.59 52.59 270 top
RM24  10_0402_1%  [R_0402]  112.24 52.59 270 top
RM25  0_0402_5%  [R_0402]  105.18 41.97 0 top
RM27  10K_0402_5%  [R_0402]  106.33 37.83 90 top
RM28  0_0402_5%  [R_0402]  106.27 40.24 90 top
RM29  0_0603_5%  [R_0603]  110.59 43.37 0 bottom
RM30  10K_0201_5%  [R_0201]  105.55 36.38 180 bottom
RM31  0_0201_5%  [R_0201]  104.05 35.71 90 bottom
RM32  0_0603_5%  [R_0603]  106.71 42.6 270 bottom
RM33  0_0603_5%  [R_0603]  102.17 41.27 90 bottom
RS32  0_1206_5%  [R_1206]  184.69 40.51 270 bottom
RS61  0_0402_5%  [R_0402]  186.91 38.81 270 bottom
RS62  100K_0402_5%  [R_0402]  178.41 41.32 90 bottom
RS63  100K_0402_5%  [R_0402]  182.23 40.7 180 bottom
RS64  0_0402_5%  [R_0402]  113.45 61.78 180 bottom
RT28  100K_0402_5%  [R_0402]  207.76 55.57 180 top
RT29  100K_0402_5%  [R_0402]  211.87 54.81 270 top
RT31  100K_0402_5%  [R_0402]  206.84 54.64 0 top
RU13  0_0402_5%  [R_0402]  22.94 38.16 0 bottom
RU14  0_0402_5%  [R_0402]  22.69 50.41 0 bottom
RU15  0_0402_5%  [R_0402]  22.69 52 0 bottom
RU16  0_0402_5%  [R_0402]  22.94 37.33 0 bottom
RU17  0_0402_5%  [R_0402]  22.69 52.76 0 bottom
RU18  0_0402_5%  [R_0402-NPM]  23.91 43.61 90 bottom
RU19  0_0402_5%  [R_0402-NPM]  24.11 39.75 180 bottom
RU20  0_0402_5%  [R_0402]  22.94 38.92 0 bottom
RU21  0_0402_5%  [R_0402-NPM]  23.15 43.61 90 bottom
RU22  0_0402_5%  [R_0402]  22.69 51.18 0 bottom
RU23  0_0402_5%  [R_0402]  22.94 36.57 0 bottom
RU24  0_0402_5%  [R_0402-NPM]  24.11 40.51 180 bottom
RU25  0_0402_5%  [R_0402-NPM]  209.06 38.48 0 bottom
RU26  0_0402_5%  [R_0402-NPM]  209.06 39.24 0 bottom
RU27  0_0402_5%  [R_0402-NPM]  205.57 39.24 0 bottom
RU28  0_0402_5%  [R_0402-NPM]  205.57 38.48 0 bottom
RU29  0_0402_5%  [R_0402]  18.3 36.57 0 bottom
RU30  0_0402_5%  [R_0402]  18.3 37.33 0 bottom
RU31  0_0402_5%  [R_0402]  18.3 38.16 0 bottom
RU32  0_0402_5%  [R_0402]  18.3 38.92 0 bottom
RU33  0_0402_5%  [R_0402]  17.99 50.59 0 bottom
RU34  0_0402_5%  [R_0402]  17.99 51.35 0 bottom
RU35  0_0402_5%  [R_0402]  17.99 52.89 0 bottom
RU36  0_0402_5%  [R_0402]  17.99 52.13 0 bottom
RW1  0_0805_5%  [R_0805]  64.46 126.11 0 top
RW2  0_0805_5%  [R_0805]  66.16 124.39 180 top
RW3  0_0402_5%  [R_0402]  71.22 135.89 0 top
RW4  0_0402_5%  [R_0402]  71.22 134.93 0 top
RW5  75K_0402_1%  [R_0402]  64.82 130.93 180 top
RW6  10K_0402_5%  [R_0402]  65.62 130.93 0 top
RW7  20K_0402_5%  [R_0402]  111.59 74.61 0 top
RW8  20K_0402_5%  [R_0402]  110.98 84.7 180 top
RW9  0_0402_5%  [R_0402]  71.22 128.47 270 top
RW10  0_0402_5%  [R_0402]  72.86 125.92 0 top
RW11  75K_0402_5%  [R_0402]  71.08 123.44 0 top
RW12  0_0402_5%  [R_0402]  103.83 75.22 0 top
RW13  0_0402_5%  [R_0402]  72.12 131.76 180 top
RW14  0_0402_5%  [R_0402]  72.12 130.93 180 top
RW15  0_0402_5%  [R_0402]  111.1 68.88 90 top
RW16  0_0402_5%  [R_0402]  72.63 129.28 180 top
RW17  0_0402_5%  [R_0402]  110.7 73.78 0 top
RW18  0_0402_5%  [R_0402]  72.04 126.75 270 top
RW19  0_0402_5%  [R_0402]  73.77 126.74 180 top
RW20  0_0402_5%  [R_0402]  72.13 132.88 180 top
RW22  1K_0201_5%  [R_0201]  71.18 124.77 0 top
RW23  1K_0201_5%  [R_0201]  71.18 124.14 0 top
RW25  0_0402_5%  [R0402_0OHM]  76.28 133.09 0 top
RW26  75K_0402_1%  [R_0402]  64.82 135.12 180 top
RW27  100K_0402_5%  [R_0402]  69.64 135.44 180 top
RW28  100K_0402_5%  [R_0402]  69.64 134.17 180 top
RW29  0_0402_5%  [R_0402]  76.36 131.31 90 top
RW30  0_0402_5%  [R_0402]  71.22 133.66 0 top
SW1  TST71-N-220-T170-S017_2P  [SW_TST71-N-220-T170-S017_2P]  220.13 64.75 90 top
T1  PAD~D  [TPC12]  97.32 72.89 180 bottom
T2  PAD~D  [TPC12]  97.32 66.92 180 bottom
T3  PAD~D  [TPC12]  78.58 73.4 0 top
T4  PAD~D  [TPC12]  78.84 68.45 0 top
T5  PAD~D  [TPC12]  103.67 91.31 0 top
T6  PAD~D  [TPC12]  99.09 57.84 270 bottom
T7  PAD~D  [TPC12]  98.27 58.86 270 bottom
T8  PAD~D  [TPC12]  97.25 69.91 180 bottom
T9  PAD~D  [TPC12]  83.65 85.02 180 bottom
T10  PAD  [TPC12]  40.03 67.56 0 top
T11  PAD  [TPC12]  33.05 69.53 0 top
T12  PAD~D  [TPC12]  72.11 122.3 0 top
T13  PAD~D  [TPC12]  69.76 125.15 0 top
T14  PAD~D  [TPC12]  72.61 124.9 0 top
T15  PAD~D  [TPC12]  74.33 132.14 0 top
T16  PAD~D  [TPC12]  73.19 132.77 0 top
T17  PAD~D  [TPC12]  70.2 133.31 0 top
T18  PAD~D  [TPC12]  20.74 84.51 180 bottom
T19  PAD~D  [TPC12]  18.77 85.09 0 top
T28  -  [TPC12]  197.52 63.3 0 top
T29  PAD  [TPC12]  221.97 64.77 0 top
T30  PAD~D  [TPC12]  67.53 62.23 180 bottom
T32  PAD~D  [TPC12]  97.76 86.1 180 bottom
T34  PAD~D  [TPC12]  27.09 27.17 0 top
T36  PAD~D  [TPC12]  63.34 112.14 0 top
T38  PAD~D  [TPC12]  64.61 108.64 0 top
T40  PAD~D  [TPC12]  69.69 126.55 0 top
T41  PAD~D  [TPC12]  73.88 124.65 0 top
T42  PAD~D  [TPC12]  77.38 93.59 0 top
T43  PAD~D  [TPC12]  65.25 95.37 0 top
T45  PAD~D  [TPC12]  65.25 94.04 0 top
T46  PAD~D  [TPC12]  63.41 95.31 0 top
T47  PAD~D  [TPC12]  65.25 92.71 0 top
T48  PAD~D  [TPC12]  61.69 95.44 0 top
T51  PAD~D  [TPC12]  64.61 98.61 0 top
T52  PAD~D  [TPC12]  106.71 87.56 0 top
T53  PAD~D  [TPC12]  69.63 108.64 0 top
T54  PAD~D  [TPC12]  63.34 98.48 0 top
T55  PAD~D  [TPC12]  63.28 97.15 0 top
T56  PAD~D  [TPC12]  62.52 99.69 0 top
T57  PAD~D  [TPC12]  63.92 99.69 0 top
T58  PAD~D  [TPC12]  65.25 99.94 0 top
T59  PAD~D  [TPC12]  62.33 100.96 0 top
T60  PAD~D  [TPC12]  63.6 100.96 0 top
T61  PAD~D  [TPC12]  64.74 101.53 0 top
T62  PAD~D  [TPC12]  63.66 102.23 0 top
T63  PAD~D  [TPC12]  64.8 102.87 0 top
TL1  350uH_NS0013LF  [BOTH_NS0013LF_16P]  17.03 73.13 270 top
TL2  350uH_NS0013LF  [BOTH_NS0013LF_16P]  17.03 64.24 90 bottom
U1  -  [SY6288C20AAC_SOT23-5]  219.05 56.14 0 top
U2  -  [NCT7718W_MSOP8]  77.54 47.73 0 top
U11  EM5209VF_SON14_2X3  [TPS22966DPUR_SON14_2X3-S]  153.33 51.33 180 top
U14  -  [SY6288C20AAC_SOT23-5]  221.78 46.16 90 top
U15  -  [SY6288C20AAC_SOT23-5]  125.77 53.6 0 top
UA1  -  [ALC3204-CG_MQFN40_5X5]  34.21 11.21 180 top
UC1  FH8068003067411-QM_FCBGA1090~D  [FH8068003067411-QM_FCBGA_1090P]  95.3 59.31 270 bottom
UC2  MC74VHC1G08DFT2G SC70 5P AND  [TC7SH08FUF_SSOP5]  104.38 89.3 180 bottom
UC3  TC7SH08FU_SSOP5  [TC7SH08FUF_SSOP5]  107.02 80.6 0 top
UC5  S IC MC74VHC1G08DFT2G SC70 5P AND  [TC7SH08FUF_SSOP5]  69.67 110.79 90 top
UC6  NL17SZ07DFT2G_SC70-5  [SN74LVC1G07DCKR_SC70-5]  67.45 107.36 90 top
UC7  NL17SZ07DFT2G_SC70-5  [SN74LVC1G07DCKR_SC70-5]  66.37 110.85 90 top
UC8  NL17SZ07DFT2G_SC70-5  [SN74LVC1G07DCKR_SC70-5]  104.76 85.49 180 bottom
UC11  W25Q128FWSIQ SOIC  [GD25LB128CSIGR_SO8]  105.25 81.27 0 bottom
UC12  NL17SZ07DFT2G_SC70-5  [SN74LVC1G07DCKR_SC70-5]  56.88 113.93 90 top
UE1  -  [KB9542Q-B_LQFP128_14X14]  133.91 51.22 180 bottom
UL1  -  [RTL8106E-CG_QFN32_4X4]  20.8 81.87 0 top
UL2  -  [SY6288C20AAC_SOT23-5]  18.71 77.96 270 top
UM1  THGBMBG8D4KBAIR_VFBGA153  [THGBMBG8D4KBAIRNHDI_VFBGA_153P]  110.7 47 0 top
UM2  -  [74AUP1G07GW_TSSOP5]  103.98 44.31 270 top
UM3  EM5209VF_DFN14_2X3  [TPS22966DPUR_SON14_2X3-S]  105.69 37.71 180 bottom
US2  -  [LNG2DMTR_LGA12_2X2]  110.68 63.32 0 bottom
UU2  -  [SY6288D20AAC_SOT23-5]  19.15 38.23 0 top
UU3  -  [SY6288D20AAC_SOT23-5]  196.69 37.4 180 bottom
UW1  -  [SY6288C20AAC_SOT23-5]  66.51 127.89 90 top
YC1  19.2MHZ_10PF_7M19200019  [Y_7M19200019_4P]  85.29 48.85 0 bottom
YC2  32.768KHZ CM7V-T1A9.0PF20PPM  [Y_9H03200031_2P]  105.88 67.83 90 top
YE1  32.768KHZ 7XZ3230001  [X_7XZ3200003_4P]  132.27 57.86 270 bottom
YL2  25MHZ_10PF_7V25000014  [Y_7V25000014_4P]  13.22 85.23 270 top

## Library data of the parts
C2 C5-C12 C14-C16 C18 C19 C21 C23 C26 C27 C34 C37 C231 C233-C235 C967 C976 C979 C980 CA2 CA26-CA28 CA51-CA53 CA474-CA480 CA482-CA493 CA495 CA497-CA499 CA501 CA502 CA504 CC1 CC2 CC4 CC6 CC7 CC9-CC14 CC16-CC25 CC27 CC29 CC30 CC33-CC36 CC38-CC40 CC42-CC44 CC46-CC48 CC52-CC56 CC58-CC63 CC73-CC77 CC80-CC84 CC86 CC88-CC93 CC95 CC96 CC272 CD1 CD2 CD6-CD10 CD19-CD26 CD28-CD33 CE1-CE9 CE17-CE21 CG27-CG34 CG47 CL5-CL8 CL10-CL12 CL18 CL24-CL27 CL29-CL32 CM1-CM8 CM17 CM26 CM27 CM29 CM30 CS3-CS6 CS13 CS14 CS16 CS18 CS30-CS36 CS42-CS44 CS109-CS115 CT14 CU16 CU20 CU24 CU25 CU29 CU30 CW1 CW4-CW10 EC2901 EC2902 EC3001 EC3002 PC1-PC4 PC11-PC15 PC301 PC302 PC305-PC308 PC315 PC317 PC501 PC502 PC505-PC508 PC515-PC517 PC1205-PC1207 PC1805-PC1807 PC2503-PC2505 PCB01 PCB02 PCB03 PCB04 PCB05 PCB06 PCB07 PCB08 PCB09-PCB19 PCB24-PCB28 PCB35-PCB37 PCG01 PCG03 PCG04 PCG05 PCG06 PCG07 PCG08 PCG09-PCG14 PCG17-PCG19 PCG124-PCG127 PCH01 PCH02 PCH09-PCH12 PCH14-PCH16 PCM01 PCM02 PCM11-PCM19 PCM22 PCM23 PCZ01 PCZ02 PCZ03 PCZ04 PCZ05 PCZ08 PCZ09-PCZ12 PCZ14-PCZ19 = C_0402
C3 C17 C35 C39 C41 C49 C225 C232 C981-C983 CA43-CA50 CC3 CC5 CC8 CC15 CD3-CD5 CD11-CD18 CE10-CE13 CE16 CE23 CE35-CE37 CG46 CL9 CL16 CL28 CM9-CM11 CM28 CS41 CU21 CU31 PCG112-PCG123 PCZ106-PCZ109 = C_0201
C4 C22 CA3 CA25 CA481 CA494 CA496 CA500 CA503 CC26 CC28 CC31 CC32 CC37 CC41 CC45 CC49-CC51 CC57 CC64-CC71 CC78 CC79 CC85 CS12 CS26 CS38 CS40 CU17-CU19 CU26 CU32 PC303 PC304 PC309-PC314 PC316 PC503 PC504 PC509-PC514 PC518-PC520 PC1201-PC1204 PC1801-PC1804 PC2501 PC2502 PCB20-PCB23 PCB29-PCB34 PCG02 PCG15 PCG16 PCG100-PCG109 PCH03 PCH04 PCH05 PCH06 PCH07 PCH08 PCH13 PCM03 PCM04 PCM05 PCM06 PCM07 PCM08 PCM09 PCM10 PCM20 PCZ06 PCZ07 PCZ13 PCZ100-PCZ105 PCZ110-PCZ119 = C_0603
CD27 PCG20 PCG110 PCG111 = C_D2
CL13 = C_1206
CLRP1 CLRP2 = SHORTPADS: User Part Number: PART#
CS39 = C_0805
CU22 CU28 = C_A
D3 D4 = BAT54C-7-F_SOT23-3
D5 = RB551V-30_SOD323-2
D11 DA6 EU2607 EU2608 EU2701 EU4012 = AZC199-02SPR7G_SOT23-3
D12 D14 ED2901 PD1 = TVNST52302AB0_SOT523-3
DA1 DA2 DA8 DA9 = L03ESDL5V0CC3-2_SOT23-3
DA5 DC6 DD1 DD2 = AZ5123-02SPR7G_SOT23-3
DA7 = BAT54CW_SOT323-3
DA10 = BAT54ATB_SOT523-3
DC1 = BAS40C_SOT23-3
DC2 DC3 = CH751H-40PT_SOD323-2
DC4 DC5 = RB751S40T1G_SOD523-2
DE1 = CK0402101V05_0402-2
DI1 = BAW56W_SOT323-3
EU2605 EU2606 = AZ1045-04F_DFN2510P10E-10-9
F1 = F_SMD1812P150TF-24
F3 = F_MF-NSMF050-2
F5 = F_T0603FF1000TM
FD1-FD4 = FIDUCIAL_C40M80
FI1 = F_1206L150PR
H1 = H_3P0
H2 H4-H7 = H_3P0-G
H8 = H_3P3
H12 = H_3P2
H13 = H_3P0X4P0
H14 = H_5P6N
HCPU1-HCPU4 = H_3P9
JDB1 = HRS_BM20B-20DS-0P4V_20P-T
JDIMM1 = LOTES_ADDR0206-P001A02_260P
JEDP1 = ACES_51540-04001-P01_40P
JFP1 = ACES_51522-00801-001_8P
JHDD1 = ACES_51625-01201-001_12P
JHDMI1 = ACON_HMRF6-AK120C_19P-T
JHP1 = YUQIU_PJ753-F07J1BE-B_7P-T
JIOB1 = ACES_51524-0160N-001_16P
JKB1 = HEFEN_AFB02-S30F1A-HF_30P-T
JKBBL1 = ACES_51575-00401-001_4P
JODD1 = ACES_50673-0120N-001_12P-T
JP5 JP10 PJP1202 PJP1802 = JUMP_43X79
JP11 PJP2501 PJP2502 PJPM03 = JUMP_43X39
JP12 JP33 JP50 PJP302 PJP502 PJPH02 PJPM02 = JUMP_43X118
JPWR1 = JXT_FP226H-004S1AM_4P
JRJ45 = SINGA_2RJ3076-078211F_8P-T
JSPK1 = ACES_50224-00401-001_4P
JSSD1 = LCN_DAN05-67306-0103_75P
JTP1 = ACES_51524-0080N-001_8P
JUSB1 JUSB2 = ACON_TARAN-9R1391_9P
JWLAN1 = LOTES_APCI0136-P001A_75P
L3 LU9 LU10 LU13 LU14 = INPAQ_MCM1012B900F06BP_4P
L4 = INPAQ_MCM1012B900F06BP_4P-NPM
L5 = MURAT_BLM15PX221SN1D_2P
LA1 LA13 = MURAT_BLM15PX330SN1D_2P
LA2 LA3 PH1 PHG1 PHG2 PHZ1 PHZ2 PR1 PR3-PR7 PR9 PR31 PR33-PR45 PR302-PR304 PR306-PR308 PR504 PR506 PR508-PR511 PR1201 PR1202 PR1204-PR1206 PR1801-PR1803 PR1805 PR1807 PR1808 PR2502-PR2504 PRB03 PRB04 PRB07 PRB08 PRB09-PRB13 PRB16-PRB18 PRB21 PRB23-PRB28 PRB30 PRB31 PRB35 PRB36 PRB38 PRB39 PRB42-PRB45 PRG01 PRG02 PRG03 PRG04 PRG05 PRG06 PRG07 PRG08 PRG09 PRG12-PRG19 PRG21-PRG28 PRG30 PRG32-PRG39 PRG41 PRG45 PRH02 PRH03 PRH04 PRH05 PRH06 PRH08 PRH09 PRH11 PRH12 PRM03 PRM06 PRM07 PRM10 PRM11 PRZ02 PRZ03 PRZ04 PRZ05 PRZ06 PRZ07 PRZ08 PRZ09-PRZ12 PRZ14-PRZ18 PRZ20 PRZ21 PRZ24 PRZ26-PRZ38 PRZ40-PRZ42 PRZ44 R5 R9 R10 R19-R22 R24-R29 R31-R35 R38-R41 R46-R49 R57 R68 R69 R72 R78-R80 R83 R86 R87 R100 R131 R182 R300 R302-R304 R926 R927 R5216-R5218 R5220 RA8 RA30-RA32 RA37-RA41 RA46-RA48 RA50-RA61 RB1-RB10 RB12 RC1-RC25 RC30-RC33 RC36-RC41 RC43 RC45-RC73 RC75-RC117 RC119-RC121 RC138-RC145 RC148 RC151 RC155-RC170 RC175 RC176 RC203 RC213 RC1146 RC1148 RC1150-RC1152 RD1-RD3 RD9-RD12 RD23 RD36 RD37 RE1 RE7 RE8 RE11 RE14 RE15 RE21 RE25-RE32 RE34-RE41 RE53-RE55 RG47 RG48 RG56 RG59-RG61 RG63-RG71 RG102-RG109 RI13 RI14 RL2-RL4 RL6-RL9 RL17 RL24 RM12-RM15 RM24 RM25 RM27 RM28 RS61-RS64 RT28 RT29 RT31 RU13-RU17 RU20 RU22 RU23 RU29-RU36 RW3-RW20 RW26-RW30 = R_0402
LE1 LE2 = MURAT_BLM15BD121SN1D_2P
LED1 = LED_LTW-295DSKS-5A_4P
LI1-LI4 LU7 LU8 LU11 LU12 = INPAQ_HCM1012GH900BP_4P-NPM
PBATT1 = ACES_50458-01001-P01_10P-T
PCB70 = C_B2
PD2 PD3 = BAV99W_SC70-3
PD5 PD6 = L03ESDL5V0CG3-2_SOT-523-3
PD14 PDB13 = PJSOT24C_SOT23-3
PD501 PD502 = RB751V-40_SOD323-2
PDB01 = LRB715FT1G_SOT323-3
PJP1-PJP3 PJP501 PJPZ1 = JUMP_43X79-NPM
PJP301 PJP1201 PJP1801 PJPG1 PJPH01 PJPM01 = JUMP_43X39-NPM
PJPB01 = JUMP_43X118-NPM
PJPDC1 = ACES_50458-00601-001_6P-T
PL1 PL2 PL4 PL511 PLB02 = 5A_Z150_1210_2P
PL3 = MURAT_BLM15AG102SN1D_2P
PL301 PL501 PLB01 PLM01 = L_7X7X3_M_2P
PL311 PL1211 PL1811 PLG11 PLH11 PLM11 PLZ11 = 5A_Z80_0805_2P
PL1201 PL1801 PLH01 = L_5X5X3_M_2P
PLG1 = L_7X7X3_M
PLZ1 = L_5X5X3_M
PQ1 = FDV301N-G_SOT23-3
PQ2 = MMST3904-7-F_SOT323-3
PQ11 PQB03 = 2N7002KW_SOT323-3
PQ12 = L2N7002DW1T1G_SC88-6
PQ13 = 2N7002KDW_SOT363-6
PQB11-PQB13 = EMB04N03H_EDFN5X6-8-5
PQB25 PQB26 = AON7702L_DFN8-5
PQB28 = LMUN5113T1G_SOT323-3
PQB29 = LTC015EUBFS8TL_UMT3F
PQB31 = DMN65D8LW-7_SOT323-3
PQB32 PQB33 = RUM002N02GT2L_VMT3
PQG1 = AON6380_DFN5X6-8-5
PQG2 = Q_N_DFN56-8-5
PQM01 PQZ1 = AONH36334_DFN3X3A8-10
PR32 PR305 PR505 PR1203 PR1804 PRB40 PRG20 PRH07 PRM01 PRZ23 RS32 = R_1206
PR301 PRB14 R7 R301 RA34 RC127 RC131-RC133 RL5 = R0603_0OHM
PR501 PRB41 PRG10 PRG29 PRG44 PRM02 PRM04 PRM05 PRZ19 PRZ22 R3 R4 R13 R36 R37 R74 R5221 R5222 RC122-RC124 RE4 RE12 RE13 RE43 RL19-RL23 RM1 RM2 RM29 RM32 RM33 = R_0603
PR502 PR503 PR507 PR2501 PRB06 PRB19 PRB20 PRB22 PRB29 PRB32 PRB37 PRG11 PRG40 PRG42 PRG43 PRH01 PRM08 PRM09 PRZ01 PRZ13 PRZ39 PRZ43 R6 R8 R77 RA33 RA35 RA36 RA62 RA65 RC34 RC35 RC42 RC126 RC128-RC130 RC134-RC136 RC1143 RD4-RD6 RE5 RE19 RE20 RE42 RL13 RW25 = R0402_0OHM
PRB01 PRB02 = R_1206_4P-D
PRB15 PRG31 PRZ25 RA63 RC125 RW1 RW2 = R_0805
PRG46 PRM12 PRZ45 = R_1206_4P-D-NPM
PU301 = SY8286BRAC_QFN20_3X3
PU501 = SY8288CRAC_QFN20_3X3
PU1201 PU1801 = RT8061AZQW_WDFN10_3X3
PU2501 = RT9059GSP_SO8
PUB01 = ISL95522HRZ-T_TQFN32_4X4
PUG1 PUZ1 = RT3601EAGQW_WQFN28_4X4
PUH01 = RT6226AGQUF_UQFN12_3X3
PUM01 = RT8207PGQW_WQFN20_3X3
Q6 Q8 Q9 Q22 QA2 = LN2306LT1G_SOT23-3
Q7 Q19 Q5029 = DDTA144VCA-7-F_SOT23-3
Q10 Q11 Q17 Q25 QG1 QS1 = DMN66D0LDW-7_SOT363-6
Q12 Q13 = 2N7002K_SOT23-3
Q14 = LMBT3904LT1G_SOT23-3
Q57 Q58 Q5027 = MESS138W-G_SOT323-3
QC1 QC9 QC10 = 2N7002_SOT23-3
QC2 = 2N7002KDWH_SOT363-6
QC3 = AP2302GN-HF_SOT23-3
QW1 = L2N7002WT1G_SC-70-3
R17 R18 RU18 RU19 RU21 RU24-RU28 = R_0402-NPM
R84 R85 RC171-RC174 RC1147 RM30 RM31 RW22 RW23 = R_0201
RA1 = R0805_0OHM
RA42 RA43 RA45 RA49 = MURAT_BLM15PD600SN1D_2P
RC1149 = R0201_0OHM
SW1 = SW_TST71-N-220-T170-S017_2P
T1-T19 T28-T30 T32 T34 T36 T38 T40-T43 T45-T48 T51-T63 = TPC12
TL1 TL2 = BOTH_NS0013LF_16P
U1 U14 U15 UL2 UW1 = SY6288C20AAC_SOT23-5
U2 = NCT7718W_MSOP8
U11 UM3 = TPS22966DPUR_SON14_2X3-S
UA1 = ALC3204-CG_MQFN40_5X5
UC1 = FH8068003067411-QM_FCBGA_1090P
UC2 UC3 UC5 = TC7SH08FUF_SSOP5
UC6-UC8 UC12 = SN74LVC1G07DCKR_SC70-5
UC11 = GD25LB128CSIGR_SO8
UE1 = KB9542Q-B_LQFP128_14X14
UL1 = RTL8106E-CG_QFN32_4X4
UM1 = THGBMBG8D4KBAIRNHDI_VFBGA_153P
UM2 = 74AUP1G07GW_TSSOP5
US2 = LNG2DMTR_LGA12_2X2
UU2 UU3 = SY6288D20AAC_SOT23-5
YC1 = Y_7M19200019_4P
YC2 = Y_9H03200031_2P
YE1 = X_7XZ3200003_4P
YL2 = Y_7V25000014_4P

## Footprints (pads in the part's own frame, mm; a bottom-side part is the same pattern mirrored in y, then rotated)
2N7002_SOT23-3
  oval 1.016x1.524 smd: 1(0,0) 2(0.965,2.083) 3(-0.965,2.083)
2N7002K_SOT23-3
  oval 1.016x1.524 smd: 1(0,0) 2(0.965,2.083) 3(-0.965,2.083)
2N7002KDW_SOT363-6
  oval 0.356x0.889 smd: 1(0,0) 2(0.65,0) 3(1.3,0) 4(1.3,1.6) 5(0.65,1.6) 6(0,1.6)
2N7002KDWH_SOT363-6
  oval 0.356x0.889 smd: 1(0,0) 2(0.65,0) 3(1.3,0) 4(1.3,1.6) 5(0.65,1.6) 6(0,1.6)
2N7002KW_SOT323-3
  oval 0.66x0.864 smd: 1(0,0) 2(0.65,1.85) 3(-0.65,1.85)
5A_Z80_0805_2P
  rect 0.813x1.397 smd: 1(0,0) 2(1.702,0)
5A_Z150_1210_2P
  rect 0.991x2.997 smd: 1(0,0) 2(2.7,0)
74AUP1G07GW_TSSOP5
  oval 0.381x1.346 smd: 1(0,0) 2(0.65,0) 3(1.3,0) 4(1.3,1.79) 5(0,1.79)
ACES_50224-00401-001_4P
  oval 0.61x1.549 smd: 1(0,0) 2(1,0) 3(2,0) 4(3,0)
  rect 1.194x1.803 smd: 5(4.3,-3.875) 6(-1.3,-3.875)
ACES_50458-00601-001_6P-T
  oval 0.559x1.6 smd: 1(0,0) 2(2,0) 3(4,0) 4(6,0) 5(8,0) 6(10,0)
  rect 1.295x2.057 smd: 7(-3.1,-5.175) 8(13.1,-5.175)
ACES_50458-01001-P01_10P-T
  oval 0.559x1.803 smd: 1(0,0) 2(2,0) 3(4,0) 4(6,0) 5(8,0) 6(10,0) 7(12,0) 8(14,0) 9(16,0) 10(18,0)
  rect 1.295x2.057 smd: 11(-3.1,-5.275) 12(21.1,-5.275)
